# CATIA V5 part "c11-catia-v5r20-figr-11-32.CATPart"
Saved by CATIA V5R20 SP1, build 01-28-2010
Part number: Part1
Bounding box of the stored display mesh (mm): x -55 to 66, y -170 to 170, z -50 to 0
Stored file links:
  D:\v5_r20\psrt_files_downloaded\c11\c11-catia-v5r20-figr-11-32.CATPart
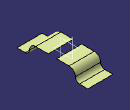
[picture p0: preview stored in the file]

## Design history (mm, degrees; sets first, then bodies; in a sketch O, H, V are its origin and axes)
Set1
  Extrude1: Element1 Sketch1, Lim1 66, Lim2 55, Direction yz-plane
  Symmetry1: ToTransfor Extrude1, Reference zx-plane
Body1 (main body)
  Sketch1 on yz-plane, origin (0, 0, 0), H (0, 1, 0), V (0, 0, 1)
    point P1 (20, 0)
    line L1 (20, 0) -> (80, 0)
    arc A1 centre (80, -30) radius 30 from (80, 0) to (110, -30) cw
    arc A2 centre (130, -30) radius 20 from (110, -30) to (130, -50) ccw
    line L2 (130, -50) -> (170, -50)
    coincidence: P1 H
    horizontal: L1 H
    tangency: A1 L1, A2 A1, L2 A2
